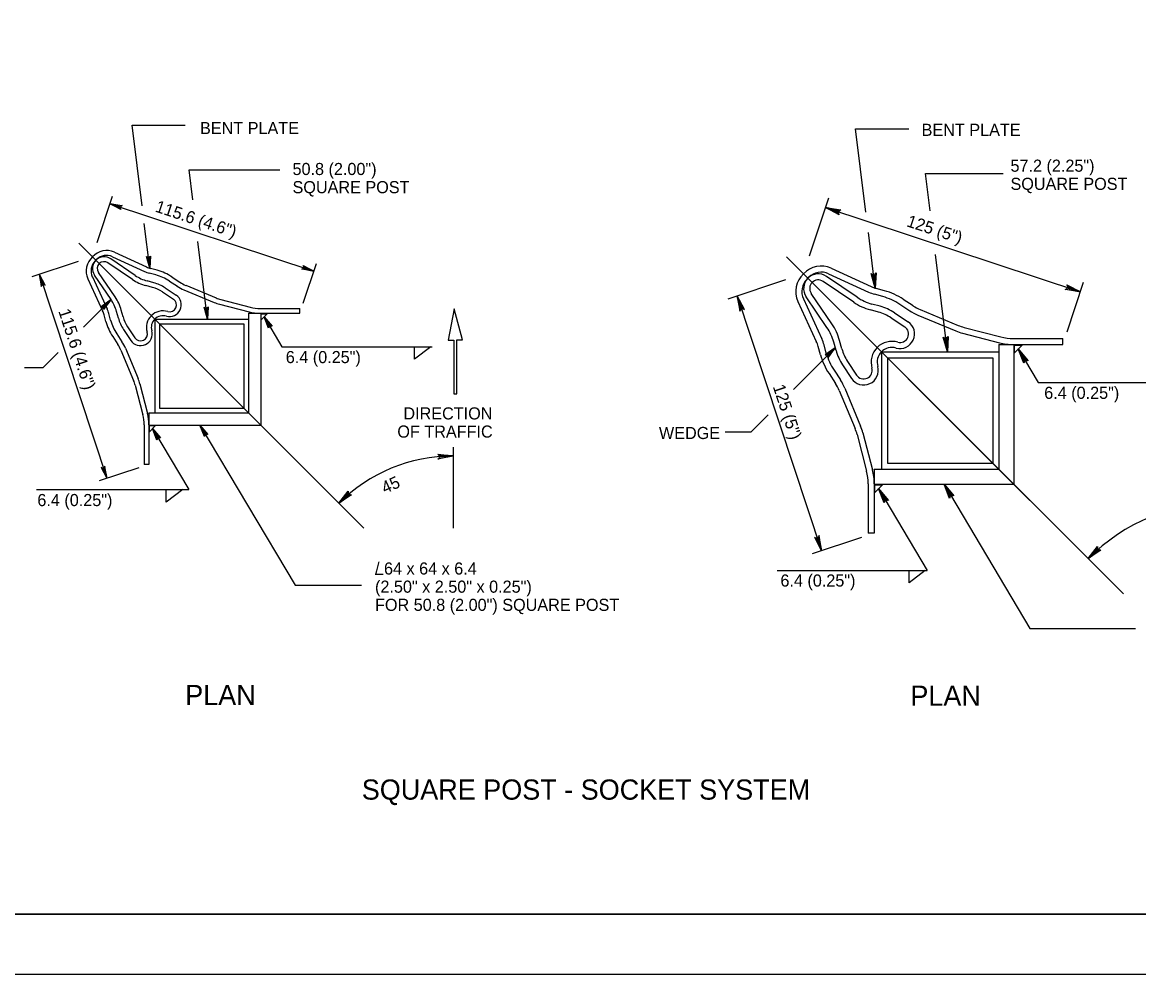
# Model space of a CAD drawing. Extents: x 644358 to 648627, y 294594 to 295782.
# Drawn here: x 646287.7 to 646564.3, y 294593.6 to 294829.5 of the extents above; entities that cross this region are included whole.
import ezdxf

# ---------------------------------------------------------------- set-up
doc = ezdxf.new("R2010")
doc.units = 0
for name, color, linetype in [('1', 7, 'Continuous'), ('2', 7, 'Continuous'), ('3', 7, 'Continuous'), ('4', 7, 'Continuous'), ('PLT-BNDY', 7, 'Continuous')]:
    doc.layers.add(name, color=color, linetype=linetype)

# ---------------------------------------------------------------- blocks, each defined once
blk = doc.blocks.new('RARROW')
at = {"layer": '3'}
blk.add_lwpolyline([(-2.2695, 0.285), (-2.184875, 0.12075), (0, 0), (-2.2695, 0.285), (-2.38575, 0.384625), (0, 0), (-2.183125, -0.108), (-2.262875, -0.2705), (0, 0), (-2.38575, -0.379125), (-2.262875, -0.2705)], dxfattribs=at)

msp = doc.modelspace()

# ---------------------------------------------------------------- linework, layer by layer
at = {"layer": '1'}
for p, q in [((646349.95, 294726.54), (646301.7, 294774.79)), ((646372.29, 294704.2), (646301.7, 294774.79)), ((646305.76, 294770.39), (646305.93, 294770.56)), ((646306.1, 294770.73), (646305.93, 294770.56)), ((646560.51, 294687.94), (646477.06, 294771.4)), ((646537.36, 294711.09), (646477.06, 294771.4)), ((646482.12, 294765.9), (646482.34, 294766.12)), ((646482.55, 294766.33), (646482.34, 294766.12)), ((646394.41, 294724.29), (646394.41, 294704.2)), ((646866.31, 294608.63), (646080.31, 294608.63)), ((646080.31, 294608.63), (646666.31, 294608.63))]:
    msp.add_line(p, q, dxfattribs=at)
at = {"layer": '2'}
for p, q in [((646317.37, 294784.03), (646314.91, 294804.02)), ((646314.91, 294804.02), (646328.06, 294804.02)), ((646496.7, 294782.46), (646494.15, 294803.13)), ((646496.62, 294783.14), (646494.15, 294803.13)), ((646494.15, 294803.13), (646507.31, 294803.13)), ((646329.93, 294785.55), (646329.02, 294792.97)), ((646329.02, 294792.97), (646351.48, 294792.97)), ((646512.6, 294782.82), (646511.45, 294792.08)), ((646511.45, 294792.08), (646530.73, 294792.08)), ((646306.27, 294774.97), (646310.07, 294786.45)), ((646309.44, 294784.55), (646359.94, 294767.84)), ((646482.76, 294771.63), (646487.51, 294785.98)), ((646486.72, 294783.61), (646549.85, 294762.71)), ((646319.28, 294768.57), (646317.91, 294779.64)), ((646499.03, 294763.63), (646497.32, 294777.47)), ((646333.58, 294755.98), (646331.21, 294775.24)), ((646516.91, 294747.89), (646513.93, 294771.97)), ((646301.52, 294770.22), (646290.04, 294766.43)), ((646357.32, 294759.94), (646360.56, 294769.74)), ((646291.94, 294767.05), (646308.65, 294716.55)), ((646476.82, 294765.7), (646462.48, 294760.95)), ((646546.58, 294752.84), (646550.63, 294765.09)), ((646309.69, 294760.81), (646302.89, 294754.01)), ((646464.85, 294761.73), (646485.74, 294698.61)), ((646348.4, 294757.31), (646346.86, 294755.76)), ((646346.86, 294755.76), (646346.86, 294757.31)), ((646346.86, 294757.31), (646348.4, 294757.31)), ((646394.68, 294758.54), (646393.2, 294750.74)), ((646396.8, 294750.82), (646394.68, 294758.54)), ((646347.63, 294756.53), (646352.04, 294749.12)), ((646352.04, 294749.12), (646389.24, 294749.12)), ((646384.87, 294746.02), (646384.87, 294749.12)), ((646388.92, 294749.12), (646384.87, 294746.02)), ((646393.2, 294750.74), (646394.65, 294750.74)), ((646394.65, 294750.74), (646394.65, 294737.49)), ((646395.35, 294737.49), (646395.35, 294750.82)), ((646395.35, 294750.82), (646396.8, 294750.82)), ((646489.12, 294748.9), (646478.74, 294738.52)), ((646535.43, 294749.55), (646533.5, 294747.62)), ((646533.5, 294747.62), (646533.5, 294749.55)), ((646533.5, 294749.55), (646535.43, 294749.55)), ((646534.46, 294748.58), (646539.4, 294740.28)), ((646296.55, 294747.67), (646292.89, 294744.01)), ((646288.25, 294744.01), (646292.89, 294744.01)), ((646539.4, 294740.28), (646577.97, 294740.28)), ((646394.65, 294737.49), (646395.35, 294737.49)), ((646472.5, 294732.28), (646468.29, 294728.07)), ((646320.73, 294729.64), (646319.18, 294728.09)), ((646319.18, 294728.09), (646319.18, 294729.64)), ((646319.18, 294729.64), (646320.73, 294729.64)), ((646331.72, 294729.74), (646355.3, 294690.09)), ((646319.96, 294728.86), (646328.94, 294713.77)), ((646461.87, 294728.07), (646468.29, 294728.07)), ((646316.55, 294719.17), (646306.75, 294715.93)), ((646291.24, 294713.77), (646328.94, 294713.77)), ((646323.32, 294710.61), (646323.32, 294713.77)), ((646327.44, 294713.77), (646323.32, 294710.61)), ((646500.84, 294714.96), (646498.91, 294713.03)), ((646498.91, 294713.03), (646498.91, 294714.96)), ((646498.91, 294714.96), (646500.84, 294714.96)), ((646499.87, 294713.99), (646511.92, 294693.74)), ((646516.08, 294715.09), (646537.33, 294679.36)), ((646495.62, 294701.88), (646483.37, 294697.82)), ((646474.7, 294693.74), (646511.92, 294693.74)), ((646507.42, 294690.68), (646507.42, 294693.74)), ((646511.42, 294693.74), (646507.42, 294690.68)), ((646375.09, 294692.79), (646377.14, 294692.79)), ((646355.3, 294690.09), (646371.78, 294690.09)), ((646537.33, 294679.36), (646563.49, 294679.36))]:
    msp.add_line(p, q, dxfattribs=at)
for centre, radius, start, end in [((646321.29, 294775.07), 6.8, 245.3297, 254.5668), ((646501.54, 294771.76), 8.5, 245.3297, 254.5668), ((646394.41, 294682.08), 40, 90, 135), ((646585.37, 294663.09), 47.5, 90, 135)]:
    msp.add_arc(centre, radius, start, end, dxfattribs=at)
at = {"layer": '3'}
for p, q in [((646315.68, 294766.8), (646309.61, 294770.91)), ((646310.04, 294771.44), (646317.95, 294767.8)), ((646310.54, 294772.53), (646318.45, 294768.89)), ((646315, 294765.8), (646308.93, 294769.92)), ((646321.1, 294768.07), (646319.48, 294768.52)), ((646488.1, 294768.58), (646497.99, 294764.03)), ((646303.96, 294765.95), (646307.6, 294758.04)), ((646305.05, 294766.45), (646308.69, 294758.54)), ((646309.69, 294760.81), (646305.58, 294766.88)), ((646310.69, 294761.49), (646306.57, 294767.56)), ((646320.25, 294764.99), (646318.63, 294765.43)), ((646320.78, 294766.91), (646319.16, 294767.36)), ((646324.18, 294765.38), (646326.11, 294764.11)), ((646324.84, 294766.38), (646326.76, 294765.11)), ((646493.68, 294760.17), (646486.09, 294765.31)), ((646494.52, 294761.41), (646486.94, 294766.56)), ((646487.47, 294767.21), (646497.36, 294762.67)), ((646319.93, 294763.83), (646318.31, 294764.28)), ((646322.42, 294762.7), (646325.12, 294760.92)), ((646323.08, 294763.7), (646325.78, 294761.93)), ((646488.29, 294754.78), (646483.14, 294762.36)), ((646501.3, 294763.01), (646499.27, 294763.57)), ((646479.88, 294760.36), (646484.42, 294750.47)), ((646481.24, 294760.98), (646485.79, 294751.09)), ((646487.04, 294753.93), (646481.9, 294761.52)), ((646500.23, 294759.15), (646498.21, 294759.71)), ((646500.9, 294761.56), (646498.88, 294762.12)), ((646505.15, 294759.64), (646507.56, 294758.05)), ((646505.97, 294760.89), (646508.38, 294759.31)), ((646308.42, 294755.39), (646307.97, 294757.01)), ((646309.58, 294755.71), (646309.13, 294757.33)), ((646311.5, 294756.24), (646311.06, 294757.86)), ((646312.66, 294756.56), (646312.21, 294758.18)), ((646343.76, 294757.41), (646343.76, 294732.74)), ((646343.76, 294757.41), (646346.68, 294757.41)), ((646346.68, 294758.61), (646356.48, 294758.61)), ((646346.68, 294757.41), (646356.48, 294757.41)), ((646346.76, 294757.41), (646346.76, 294729.74)), ((646356.48, 294757.41), (646356.48, 294758.61)), ((646499.84, 294757.7), (646497.81, 294758.26)), ((646503.77, 294757.55), (646507.16, 294755.32)), ((646313.79, 294754.07), (646315.57, 294751.37)), ((646320.51, 294755.98), (646320.51, 294732.74)), ((646320.51, 294755.98), (646343.76, 294755.98)), ((646321.71, 294754.78), (646321.71, 294733.94)), ((646321.71, 294754.78), (646342.56, 294754.78)), ((646342.56, 294754.78), (646342.56, 294733.94)), ((646502.95, 294756.29), (646506.33, 294754.07)), ((646310.11, 294751.66), (646311.38, 294749.73)), ((646311.12, 294752.31), (646312.38, 294750.39)), ((646312.79, 294753.41), (646314.56, 294750.71)), ((646533.28, 294751.18), (646545.53, 294751.18)), ((646545.53, 294749.68), (646545.53, 294751.18)), ((646485.45, 294747.16), (646484.89, 294749.18)), ((646486.9, 294747.56), (646486.34, 294749.58)), ((646489.31, 294748.22), (646488.75, 294750.25)), ((646490.75, 294748.62), (646490.19, 294750.65)), ((646529.62, 294749.68), (646529.62, 294718.84)), ((646529.62, 294749.68), (646533.28, 294749.68)), ((646533.28, 294749.68), (646545.53, 294749.68)), ((646533.37, 294749.68), (646533.37, 294715.09)), ((646500.57, 294747.89), (646500.57, 294718.84)), ((646500.57, 294747.89), (646529.62, 294747.89)), ((646502.07, 294746.39), (646502.07, 294720.34)), ((646502.07, 294746.39), (646528.12, 294746.39)), ((646528.12, 294746.39), (646528.12, 294720.34)), ((646488.82, 294743.31), (646490.41, 294740.9)), ((646490.91, 294744.68), (646493.13, 294741.3)), ((646492.16, 294745.51), (646494.39, 294742.12)), ((646487.57, 294742.49), (646489.15, 294740.07)), ((646319.08, 294732.74), (646343.76, 294732.74)), ((646319.08, 294732.74), (646319.08, 294729.81)), ((646321.71, 294733.94), (646342.56, 294733.94)), ((646317.88, 294729.81), (646317.88, 294720.01)), ((646319.08, 294729.81), (646319.08, 294720.01)), ((646319.08, 294729.74), (646346.76, 294729.74)), ((646319.08, 294720.01), (646317.88, 294720.01)), ((646498.78, 294718.84), (646529.62, 294718.84)), ((646498.78, 294718.84), (646498.78, 294715.18)), ((646502.07, 294720.34), (646528.12, 294720.34)), ((646497.28, 294715.18), (646497.28, 294702.93)), ((646498.78, 294715.18), (646498.78, 294702.93)), ((646498.78, 294715.09), (646533.37, 294715.09)), ((646498.78, 294702.93), (646497.28, 294702.93))]:
    msp.add_line(p, q, dxfattribs=at)
for points in [[(646327.74, 294763.24), (646335.23, 294760.11)], [(646328.2, 294764.35), (646335.69, 294761.21)], [(646336.59, 294759.65), (646343.88, 294757.76)], [(646336.89, 294760.81), (646344.18, 294758.93)], [(646509.6, 294756.97), (646518.96, 294753.05)], [(646510.18, 294758.35), (646519.54, 294754.43)], [(646521.03, 294753.93), (646530.15, 294751.57)], [(646520.66, 294752.48), (646529.77, 294750.12)], [(646313.25, 294748.75), (646316.39, 294741.26)], [(646312.15, 294748.29), (646315.28, 294740.8)], [(646315.68, 294739.61), (646317.57, 294732.31)], [(646316.84, 294739.91), (646318.73, 294732.61)], [(646490.11, 294738.28), (646494.02, 294728.91)], [(646491.49, 294738.86), (646495.41, 294729.49)], [(646494.53, 294727.42), (646496.88, 294718.31)], [(646495.98, 294727.8), (646498.34, 294718.69)]]:
    msp.add_lwpolyline(points, dxfattribs=at)
for centre, radius, start, end in [((646308.23, 294767.91), 4.7, 132.0461, 204.6703), ((646307.98, 294768.51), 2.9, 135, 214.1353), ((646308.58, 294768.26), 4.7, 65.3297, 137.9539), ((646307.98, 294768.51), 2.9, 55.8647, 135), ((646308.58, 294768.26), 3.5, 65.3297, 135), ((646308.23, 294767.91), 3.5, 135, 204.6703), ((646307.98, 294768.51), 1.7, 135, 214.1353), ((646307.98, 294768.51), 1.7, 55.8647, 135), ((646321.29, 294775.07), 8, 245.3297, 254.5668), ((646317.59, 294755.35), 13.2, 56.6854, 74.5668), ((646485.65, 294763.24), 5.88, 65.3297, 137.9539), ((646321.29, 294775.07), 11.2, 235.8647, 254.5668), ((646321.29, 294775.07), 10, 235.8647, 254.5668), ((646317.59, 294755.35), 10, 56.6854, 74.5668), ((646317.59, 294755.35), 12, 56.6854, 74.5668), ((646331.6, 294772.46), 8.8, 236.6854, 247.3023), ((646485.22, 294762.81), 5.88, 132.0461, 204.6703), ((646485.22, 294762.81), 4.38, 135, 204.6703), ((646484.9, 294763.56), 3.62, 135, 214.1353), ((646484.9, 294763.56), 3.62, 55.8647, 135), ((646485.65, 294763.24), 4.38, 65.3297, 135), ((646484.9, 294763.56), 2.12, 135, 214.1353), ((646484.9, 294763.56), 2.12, 55.8647, 135), ((646317.59, 294755.35), 8.8, 56.6854, 74.5668), ((646331.6, 294772.46), 10, 236.6854, 247.3023), ((646501.54, 294771.76), 10, 245.3297, 254.5668), ((646496.91, 294747.1), 16.5, 56.6854, 74.5668), ((646301.42, 294755.2), 10, 15.4332, 34.1353), ((646301.42, 294755.2), 11.2, 15.4332, 34.1353), ((646324.19, 294759.5), 2.9, 254.3625, 56.685), ((646324.19, 294759.5), 1.7, 254.3625, 56.685), ((646339.09, 294769.33), 10, 247.3023, 255.4975), ((646339.09, 294769.33), 8.8, 247.3023, 255.4975), ((646501.54, 294771.76), 14, 235.8647, 254.5668), ((646501.54, 294771.76), 12.5, 235.8647, 254.5668), ((646496.91, 294747.1), 15, 56.6854, 74.5668), ((646301.42, 294755.2), 6.8, 15.4332, 24.6703), ((646301.42, 294755.2), 8, 15.4332, 24.6703), ((646322.56, 294753.92), 4.1, 134.7773, 196.7828), ((646322.57, 294753.93), 4.1, 73.2172, 135.2227), ((646322.57, 294753.93), 2.9, 73.2172, 135.2227), ((646346.68, 294768.61), 11.2, 255.4975, 270), ((646346.68, 294768.61), 10, 255.4975, 270), ((646496.91, 294747.1), 11, 56.6854, 74.5668), ((646496.91, 294747.1), 12.5, 56.6854, 74.5668), ((646514.42, 294768.5), 12.5, 236.6854, 247.3023), ((646514.42, 294768.5), 11, 236.6854, 247.3023), ((646321.14, 294758.91), 13.2, 195.4332, 213.3146), ((646321.14, 294758.91), 12, 195.4332, 213.3146), ((646321.14, 294758.91), 10, 195.4332, 213.3146), ((646321.14, 294758.91), 8.8, 195.4332, 213.3146), ((646322.56, 294753.92), 2.9, 134.7773, 196.7828), ((646476.7, 294746.92), 12.5, 15.4332, 34.1353), ((646476.7, 294746.92), 14, 15.4332, 34.1353), ((646505.16, 294752.3), 3.62, 254.3625, 56.685), ((646505.16, 294752.3), 2.12, 254.3625, 56.685), ((646523.79, 294764.58), 11, 247.3023, 255.4975), ((646316.99, 294752.3), 2.9, 213.315, 15.6375), ((646316.99, 294752.3), 1.7, 213.315, 15.6375), ((646523.79, 294764.58), 12.5, 247.3023, 255.4975), ((646533.28, 294763.68), 12.5, 255.4975, 270), ((646304.03, 294744.89), 8.8, 22.6977, 33.3146), ((646304.03, 294744.89), 10, 22.6977, 33.3146), ((646476.7, 294746.92), 8.5, 15.4332, 24.6703), ((646476.7, 294746.92), 10, 15.4332, 24.6703), ((646501.36, 294751.55), 11, 195.4332, 213.3146), ((646503.12, 294745.32), 5.12, 134.7773, 196.7828), ((646503.14, 294745.34), 5.12, 73.2172, 135.2227), ((646503.14, 294745.34), 3.62, 73.2172, 135.2227), ((646533.28, 294763.68), 14, 255.4975, 270), ((646501.36, 294751.55), 16.5, 195.4332, 213.3146), ((646501.36, 294751.55), 15, 195.4332, 213.3146), ((646501.36, 294751.55), 12.5, 195.4332, 213.3146), ((646503.12, 294745.32), 3.62, 134.7773, 196.7828), ((646496.16, 294743.29), 3.62, 213.315, 15.6375), ((646496.16, 294743.29), 2.12, 213.315, 15.6375), ((646307.16, 294737.4), 8.8, 14.5025, 22.6977), ((646307.16, 294737.4), 10, 14.5025, 22.6977), ((646479.96, 294734.03), 11, 22.6977, 33.3146), ((646479.96, 294734.03), 12.5, 22.6977, 33.3146), ((646307.88, 294729.81), 10, 0, 14.5025), ((646307.88, 294729.81), 11.2, 0, 14.5025), ((646483.88, 294724.67), 12.5, 14.5025, 22.6977), ((646483.88, 294724.67), 11, 14.5025, 22.6977), ((646484.78, 294715.18), 12.5, 0, 14.5025), ((646484.78, 294715.18), 14, 0, 14.5025)]:
    msp.add_arc(centre, radius, start, end, dxfattribs=at)
at = {"layer": 'PLT-BNDY'}
msp.add_lwpolyline([(646040.31, 295187.63), (646881.31, 295187.63), (646881.31, 294593.63), (646040.31, 294593.63)], close=True, dxfattribs=at)

# ---------------------------------------------------------------- block references
at = {"layer": '2'}
for p, xscale, yscale, rotation in [((646309.44, 294784.55), 1.2574347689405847, 1.3092961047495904, 161.72234238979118), ((646486.72, 294783.61), 1.571793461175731, 1.6366201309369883, 161.72234238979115), ((646319.28, 294768.57), 1.2574347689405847, 1.3092961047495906, -83.5643877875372), ((646359.94, 294767.84), 1.2574347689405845, 1.3092961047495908, -18.430831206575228), ((646291.94, 294767.05), 1.2574347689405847, -1.3092961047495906, 108.27765761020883), ((646499.02, 294763.63), 1.571793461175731, 1.6366201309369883, -83.5643877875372), ((646549.85, 294762.71), 1.5717934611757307, 1.636620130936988, -18.430831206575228), ((646309.69, 294760.81), 1.257434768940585, -1.3092961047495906, 44.86487671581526), ((646464.85, 294761.73), 1.571793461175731, -1.6366201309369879, 108.27765761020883), ((646333.58, 294755.98), 1.2574347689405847, 1.3092961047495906, -83.5643877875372), ((646347.63, 294756.53), 1.257434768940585, 1.3092961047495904, 120.80429784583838), ((646516.9, 294747.89), 1.571793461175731, 1.6366201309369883, -83.5643877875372), ((646489.12, 294748.9), 1.257434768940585, -1.3092961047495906, 44.86487671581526), ((646534.46, 294748.58), 1.5717934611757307, 1.636620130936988, 120.80429784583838), ((646319.96, 294728.86), 1.257434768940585, 1.3092961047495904, 120.80429784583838), ((646331.72, 294729.74), 1.257434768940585, 1.3092961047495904, 120.80429784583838), ((646394.41, 294722.08), 1.571793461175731, 1.6366201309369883, 2.441123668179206), ((646308.65, 294716.55), 1.2574347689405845, -1.3092961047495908, -71.56916879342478), ((646516.08, 294715.09), 1.5717934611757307, 1.636620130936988, 120.80429784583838), ((646366.12, 294710.37), 1.571793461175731, 1.6366201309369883, -136.74013509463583), ((646499.87, 294713.99), 1.5717934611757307, 1.636620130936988, 120.80429784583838), ((646485.74, 294698.61), 1.5717934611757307, -1.636620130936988, -71.56916879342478), ((646551.78, 294696.68), 1.571793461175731, 1.6366201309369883, -136.74013509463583)]:
    msp.add_blockref('RARROW', p, dxfattribs=dict(at, xscale=xscale, yscale=yscale, rotation=rotation))

# ---------------------------------------------------------------- texts
for s, height, p in [('BENT PLATE', 3, (646331.73, 294801.79)), ('BENT PLATE', 3, (646510.52, 294801.36)), ('57.2 (2.25")', 3, (646532.53, 294792.48)), ('50.8 (2.00")', 3, (646354.65, 294791.66)), ('SQUARE POST', 3, (646354.65, 294787.16)), ('SQUARE POST', 3, (646532.53, 294787.98)), ('6.4 (0.25")', 3, (646352.98, 294745.08)), ('6.4 (0.25")', 3, (646540.89, 294736.23)), ('DIRECTION', 3, (646382.12, 294731.13)), ('OF TRAFFIC', 3, (646380.62, 294726.63)), ('WEDGE', 3, (646445.43, 294726.28)), ('6.4 (0.25")', 3, (646291.43, 294709.67)), ('/ 64 x 64 x 6.4', 3, (646375.09, 294692.72)), ('(2.50" x 2.50" x 0.25")', 3, (646375.09, 294688.22)), ('6.4 (0.25")', 3, (646475.53, 294689.74)), ('FOR 50.8 (2.00") SQUARE POST', 3, (646375.09, 294683.72)), ('PLAN', 5, (646328.06, 294660.38)), ('PLAN', 5, (646507.73, 294660.21)), ('SQUARE POST - SOCKET SYSTEM', 5, (646371.81, 294636.97))]:
    msp.add_text(s, height=height, dxfattribs=at).set_placement(p)
msp.add_text('45', height=3, rotation=24.8378, dxfattribs=at).set_placement((646377.55, 294712.65))
at = {"layer": '4'}
for s, rotation, p in [('115.6 (4.6")', 341.6869, (646320.42, 294782.64)), ('125 (5")', 341.6869, (646506.6, 294779.02)), ('115.6 (4.6")', 288.3131, (646296.58, 294757.98)), ('125 (5")', 288.3131, (646473.61, 294739.28))]:
    msp.add_text(s, height=3, rotation=rotation, dxfattribs=at).set_placement(p)

doc.saveas('drawing.dxf')
